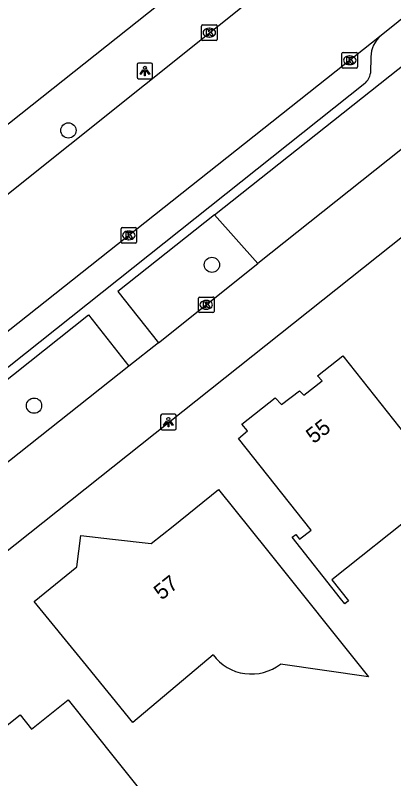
# Model space of a CAD drawing. Extents: x 159503 to 160347, y 382525 to 383272.
# Drawn here: x 159926.86 to 159951.11, y 383063.74 to 383112.66 of the extents above; entities that cross this region are included whole.
import ezdxf

# ---------------------------------------------------------------- set-up
doc = ezdxf.new("R2010")
doc.units = 0
for name, color, linetype in [('IMGEO_Boom', 7, 'Continuous'), ('IMGEO_Groenvoorziening', 7, 'Continuous'), ('IMGEO_Kolk', 7, 'Continuous'), ('IMGEO_Lichtpunt', 7, 'Continuous'), ('IMGEO_Pand', 7, 'Continuous'), ('IMGEO_Pand_nummerreeks', 7, 'Continuous'), ('IMGEO_Rijbaan_lokaal_open', 7, 'Continuous'), ('IMGEO_Voetpad_open', 7, 'Continuous')]:
    doc.layers.add(name, color=color, linetype=linetype)

msp = doc.modelspace()

# ---------------------------------------------------------------- linework, layer by layer
at = {"layer": 'IMGEO_Boom'}
for centre in [(159930.264, 383105.285), (159939.462, 383096.673), (159928.063, 383087.649)]:
    msp.add_circle(centre, 0.489, dxfattribs=at)
at = {"layer": 'IMGEO_Groenvoorziening'}
msp.add_lwpolyline([(159942.411, 383096.752), (159939.635, 383099.886)], dxfattribs=at)
at = {"layer": 'IMGEO_Kolk'}
for p, q in [((159938.796, 383111.122), (159938.796, 383111.974)), ((159938.871, 383112.048), (159939.723, 383112.048)), ((159939.284, 383111.828), (159939.309, 383111.828)), ((159939.797, 383111.974), (159939.797, 383111.122)), ((159939.307, 383111.268), (159939.282, 383111.268)), ((159939.723, 383111.048), (159938.871, 383111.048)), ((159947.791, 383109.357), (159947.791, 383110.209)), ((159947.866, 383110.283), (159948.718, 383110.283)), ((159948.792, 383110.209), (159948.792, 383109.357)), ((159948.279, 383110.063), (159948.304, 383110.063)), ((159948.718, 383109.283), (159947.866, 383109.283)), ((159948.302, 383109.503), (159948.277, 383109.503)), ((159933.637, 383098.135), (159933.637, 383098.987)), ((159933.712, 383099.061), (159934.564, 383099.061)), ((159934.638, 383098.987), (159934.638, 383098.135)), ((159934.125, 383098.841), (159934.15, 383098.841)), ((159934.564, 383098.061), (159933.712, 383098.061)), ((159934.148, 383098.281), (159934.123, 383098.281)), ((159938.597, 383093.686), (159938.597, 383094.538)), ((159938.672, 383094.612), (159939.524, 383094.612)), ((159939.598, 383094.538), (159939.598, 383093.686)), ((159939.085, 383094.392), (159939.11, 383094.392)), ((159939.524, 383093.612), (159938.672, 383093.612)), ((159939.108, 383093.832), (159939.083, 383093.832))]:
    msp.add_line(p, q, dxfattribs=at)
for points in [[(159938.796, 383111.122), (159938.796, 383111.974)], [(159938.871, 383112.048), (159939.723, 383112.048)], [(159939.117, 383111.748), (159939.24, 383111.748), (159939.24, 383111.597), (159939.37, 383111.748), (159939.534, 383111.748), (159939.388, 383111.597), (159939.541, 383111.348), (159939.389, 383111.348), (159939.304, 383111.512), (159939.24, 383111.445), (159939.24, 383111.348), (159939.117, 383111.348), (159939.117, 383111.748)], [(159939.797, 383111.974), (159939.797, 383111.122)], [(159939.723, 383111.048), (159938.871, 383111.048)], [(159947.791, 383109.357), (159947.791, 383110.209)], [(159947.866, 383110.283), (159948.718, 383110.283)], [(159948.792, 383110.209), (159948.792, 383109.357)], [(159948.112, 383109.983), (159948.235, 383109.983), (159948.235, 383109.832), (159948.365, 383109.983), (159948.529, 383109.983), (159948.383, 383109.832), (159948.536, 383109.583), (159948.384, 383109.583), (159948.299, 383109.747), (159948.235, 383109.68), (159948.235, 383109.583), (159948.112, 383109.583), (159948.112, 383109.983)], [(159948.718, 383109.283), (159947.866, 383109.283)], [(159933.637, 383098.135), (159933.637, 383098.987)], [(159933.712, 383099.061), (159934.564, 383099.061)], [(159934.638, 383098.987), (159934.638, 383098.135)], [(159933.958, 383098.761), (159934.081, 383098.761), (159934.081, 383098.61), (159934.211, 383098.761), (159934.375, 383098.761), (159934.229, 383098.61), (159934.382, 383098.361), (159934.23, 383098.361), (159934.145, 383098.525), (159934.081, 383098.458), (159934.081, 383098.361), (159933.958, 383098.361), (159933.958, 383098.761)], [(159934.564, 383098.061), (159933.712, 383098.061)], [(159938.597, 383093.686), (159938.597, 383094.538)], [(159938.672, 383094.612), (159939.524, 383094.612)], [(159939.598, 383094.538), (159939.598, 383093.686)], [(159938.918, 383094.312), (159939.041, 383094.312), (159939.041, 383094.161), (159939.171, 383094.312), (159939.335, 383094.312), (159939.189, 383094.161), (159939.342, 383093.912), (159939.19, 383093.912), (159939.105, 383094.076), (159939.041, 383094.009), (159939.041, 383093.912), (159938.918, 383093.912), (159938.918, 383094.312)], [(159939.524, 383093.612), (159938.672, 383093.612)]]:
    msp.add_lwpolyline(points, dxfattribs=at)
for centre, start, end in [((159938.873, 383111.972), 91.552, 178.448), ((159938.873, 383111.972), 91.552, 178.448), ((159939.721, 383111.972), 1.552, 88.448), ((159939.721, 383111.972), 1.552, 88.448), ((159938.873, 383111.124), 181.552, 268.448), ((159938.873, 383111.124), 181.552, 268.448), ((159939.721, 383111.124), 271.552, 358.448), ((159939.721, 383111.124), 271.552, 358.448), ((159947.868, 383110.207), 91.552, 178.448), ((159947.868, 383110.207), 91.552, 178.448), ((159948.716, 383110.207), 1.552, 88.448), ((159948.716, 383110.207), 1.552, 88.448), ((159947.868, 383109.359), 181.552, 268.448), ((159947.868, 383109.359), 181.552, 268.448), ((159948.716, 383109.359), 271.552, 358.448), ((159948.716, 383109.359), 271.552, 358.448), ((159933.714, 383098.985), 91.552, 178.448), ((159933.714, 383098.985), 91.552, 178.448), ((159934.562, 383098.985), 1.552, 88.448), ((159934.562, 383098.985), 1.552, 88.448), ((159933.714, 383098.137), 181.552, 268.448), ((159933.714, 383098.137), 181.552, 268.448), ((159934.562, 383098.137), 271.552, 358.448), ((159934.562, 383098.137), 271.552, 358.448), ((159938.674, 383094.536), 91.552, 178.448), ((159938.674, 383094.536), 91.552, 178.448), ((159939.522, 383094.536), 1.552, 88.448), ((159939.522, 383094.536), 1.552, 88.448), ((159938.674, 383093.688), 181.552, 268.448), ((159938.674, 383093.688), 181.552, 268.448), ((159939.522, 383093.688), 271.552, 358.448), ((159939.522, 383093.688), 271.552, 358.448)]:
    msp.add_arc(centre, 0.0765, start, end, dxfattribs=at)
for centre, major_axis, ratio, start_param, end_param in [((159939.283, 383111.548), (-0.387, 0.002), 0.722429, 4.712389, 7.853982), ((159939.308, 383111.548), (-0.39, 0.002), 0.717154, 1.570796, 4.712389), ((159948.278, 383109.783), (-0.387, 0.002), 0.722429, 4.712389, 7.853982), ((159948.303, 383109.783), (-0.39, 0.002), 0.717154, 1.570796, 4.712389), ((159934.124, 383098.561), (-0.387, 0.002), 0.722429, 4.712389, 7.853982), ((159934.149, 383098.561), (-0.39, 0.002), 0.717154, 1.570796, 4.712389), ((159939.084, 383094.112), (-0.387, 0.002), 0.722429, 4.712389, 7.853982), ((159939.109, 383094.112), (-0.39, 0.002), 0.717154, 1.570796, 4.712389)]:
    msp.add_ellipse(centre, major_axis=major_axis, ratio=ratio, start_param=start_param, end_param=end_param, dxfattribs=at)
at = {"layer": 'IMGEO_Lichtpunt'}
for p, q in [((159934.667, 383109.5), (159934.667, 383108.693)), ((159934.667, 383109.5), (159934.667, 383108.693)), ((159935.569, 383109.595), (159934.761, 383109.595)), ((159935.569, 383109.595), (159934.761, 383109.595)), ((159935.663, 383108.693), (159935.663, 383109.5)), ((159935.663, 383108.693), (159935.663, 383109.5)), ((159934.761, 383108.599), (159935.569, 383108.599)), ((159934.761, 383108.599), (159935.569, 383108.599)), ((159936.173, 383087.001), (159936.173, 383086.194)), ((159936.173, 383087.001), (159936.173, 383086.194)), ((159937.075, 383087.096), (159936.267, 383087.096)), ((159937.075, 383087.096), (159936.267, 383087.096)), ((159937.169, 383086.194), (159937.169, 383087.001)), ((159937.169, 383086.194), (159937.169, 383087.001)), ((159936.267, 383086.1), (159937.075, 383086.1)), ((159936.267, 383086.1), (159937.075, 383086.1))]:
    msp.add_line(p, q, dxfattribs=at)
for points in [[(159935.041, 383109.164), (159935.08, 383109.136), (159934.892, 383108.874), (159934.854, 383108.901), (159935.041, 383109.164)], [(159935.253, 383109.136), (159935.291, 383109.163), (159935.478, 383108.901), (159935.439, 383108.873), (159935.253, 383109.136)], [(159935.143, 383109.116), (159935.19, 383109.116), (159935.19, 383108.794), (159935.143, 383108.794), (159935.143, 383109.116)], [(159936.547, 383086.665), (159936.586, 383086.637), (159936.398, 383086.375), (159936.36, 383086.402), (159936.547, 383086.665)], [(159936.759, 383086.637), (159936.797, 383086.664), (159936.984, 383086.402), (159936.945, 383086.374), (159936.759, 383086.637)], [(159936.649, 383086.617), (159936.696, 383086.617), (159936.696, 383086.295), (159936.649, 383086.295), (159936.649, 383086.617)]]:
    msp.add_lwpolyline(points, dxfattribs=at)
for centre in [(159935.166, 383109.298), (159936.672, 383086.799)]:
    msp.add_circle(centre, 0.0994, dxfattribs=at)
for centre, start, end in [((159934.761, 383109.5), 90, 180), ((159934.761, 383109.5), 90, 180), ((159935.569, 383109.5), 0, 90), ((159935.569, 383109.5), 0, 90), ((159934.761, 383108.693), 180, 270), ((159934.761, 383108.693), 180, 270), ((159935.569, 383108.693), 270, 0), ((159935.569, 383108.693), 270, 360), ((159936.267, 383087.001), 90, 180), ((159936.267, 383087.001), 90, 180), ((159937.075, 383087.001), 0, 90), ((159937.075, 383087.001), 0, 90), ((159936.267, 383086.194), 180, 270), ((159936.267, 383086.194), 180, 270), ((159937.075, 383086.194), 270, 0), ((159937.075, 383086.194), 270, 360)]:
    msp.add_arc(centre, 0.0946, start, end, dxfattribs=at)
at = {"layer": 'IMGEO_Pand'}
for points in [[(159947.14, 383076.492), (159948.212, 383075.142), (159947.976, 383074.956), (159947.704, 383075.299), (159944.599, 383079.217), (159944.843, 383079.389), (159945.082, 383079.092), (159945.83, 383079.665), (159941.166, 383085.541), (159941.741, 383086.028), (159941.379, 383086.454), (159943.519, 383088.148), (159943.926, 383087.731), (159945.063, 383088.61), (159945.354, 383088.315), (159946.515, 383089.246), (159946.229, 383089.568), (159947.847, 383090.84), (159951.91, 383085.717)], [(159939.532, 383071.681), (159934.392, 383067.356), (159931.235, 383071.229), (159928.077, 383075.105), (159930.805, 383077.328), (159931.066, 383079.321), (159933.084, 383079.097), (159935.572, 383078.82), (159936.97, 383079.938), (159939.893, 383082.276), (159943.016, 383078.371), (159949.487, 383070.281), (159943.856, 383071.093)], [(159952.68, 383080.884), (159947.14, 383076.492)], [(159937.475, 383059.76), (159935.132, 383057.887), (159931.423, 383062.527), (159928.167, 383059.923), (159927.753, 383059.087), (159926.961, 383058.405), (159926.066, 383058.258), (159922.824, 383055.666), (159922.187, 383056.462), (159919.064, 383060.367), (159921.485, 383062.302), (159920.86, 383063.083), (159920.149, 383062.514), (159917.07, 383066.364), (159922.239, 383070.497), (159924.831, 383067.256), (159924.121, 383066.688), (159924.746, 383065.907), (159927.168, 383067.843), (159927.899, 383066.93), (159930.243, 383068.804), (159933.366, 383064.899), (159937.475, 383059.76)]]:
    msp.add_lwpolyline(points, dxfattribs=at)
msp.add_arc((159941.984, 383073.52), 3.065, 216.873, 307.6392, dxfattribs=at)
at = {"layer": 'IMGEO_Rijbaan_lokaal_open'}
for points in [[(159925.553, 383100.562), (159944.715, 383115.876)], [(159954.759, 383114.972), (159950.297, 383111.374)], [(159950.297, 383111.374), (159911.357, 383080.502)], [(159957.398, 383108.683), (159942.411, 383096.752)], [(159961.699, 383106.426), (159884.908, 383045.395), (159855.273, 383021.828)], [(159936.037, 383091.678), (159942.411, 383096.752)], [(159936.037, 383091.678), (159934.146, 383090.179)], [(159934.146, 383090.179), (159909.329, 383070.5)]]:
    msp.add_lwpolyline(points, dxfattribs=at)
at = {"layer": 'IMGEO_Voetpad_open'}
for points in [[(159838.776, 383036.162), (160000, 383164.155), (160003.86, 383167.245)], [(159939.635, 383099.886), (159954.362, 383111.559), (159954.685, 383111.851)], [(159949.643, 383109.993), (159949.62, 383108.944)], [(159949.26, 383108.299), (159914.641, 383080.756)], [(159939.635, 383099.886), (159933.423, 383094.963), (159936.037, 383091.678)], [(159906.787, 383073.771), (159931.545, 383093.463), (159934.146, 383090.179)]]:
    msp.add_lwpolyline(points, dxfattribs=at)
for centre, radius, start, end in [((159951.473, 383109.972), 1.83, 129.989, 179.3294), ((159948.52, 383109.135), 1.116, 311.5049, 350.1599)]:
    msp.add_arc(centre, radius, start, end, dxfattribs=at)

# ---------------------------------------------------------------- texts
at = {"layer": 'IMGEO_Pand_nummerreeks'}
for s, rotation, p in [('55', 37.7071, (159945.979, 383085.172)), ('57', 38.6498, (159936.237, 383075.152))]:
    msp.add_text(s, height=1, rotation=rotation, dxfattribs=at).set_placement(p)

doc.saveas('drawing.dxf')
